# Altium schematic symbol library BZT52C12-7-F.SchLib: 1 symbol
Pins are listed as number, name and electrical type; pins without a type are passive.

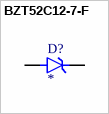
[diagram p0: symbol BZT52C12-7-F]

## BZT52C12-7-F
designator D?
Zener Diode 12V 5.3% 500mW SOD123 ¦ Diodes Inc BZT52C12-7-F; MF: Diodes Inc.
footprint DIO_BZT52C12-7-F
pins: 1 K, 2 A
